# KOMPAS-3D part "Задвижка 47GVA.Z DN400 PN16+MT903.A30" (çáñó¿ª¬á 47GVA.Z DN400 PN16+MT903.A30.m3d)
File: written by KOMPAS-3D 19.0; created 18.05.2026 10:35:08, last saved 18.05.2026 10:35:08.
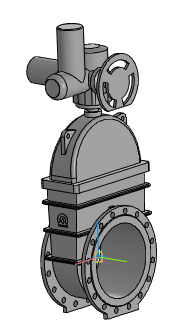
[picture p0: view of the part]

Document properties: Автор: Энергия; Полное имя файла: ..\Задвижка 47GVA.Z DN350_DN1200+MT903.A\Задвижка 47GVA.Z DN400 PN16+MT903.A30.a3d

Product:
- Part/product: Задвижка 47GVA.Z DN400 PN16+MT903.A30
    Масса: 751.45
  - Body: Электропривод МТ903.А30 без блока управления
      Масса: 163.268
  - Body: Задвижка 47GV.Z DN400 PN16 без исполнительного механизма
      Масса: 588.182

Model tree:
1. Операция без истории:1
2. Операция без истории:2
